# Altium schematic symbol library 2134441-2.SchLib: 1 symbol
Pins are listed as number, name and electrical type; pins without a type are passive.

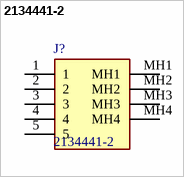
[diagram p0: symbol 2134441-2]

## 2134441-2
designator J?
Body Features: Offset .88 MM | Shell Plating Material Tin over Nickel | Shell Plating Finish Matte | Connector Profile Micro | Configuration Features: Number of Positions 5 | Number of Ports 1 | Contact Features: Contact Mating Area Plating Material Thickness .76 MICM | Contact Current Rating (Max) 1.8 AMP | Contact Mating Area Plating Material Gold | Contact Mating Area Plating Material Thickness 29.52 MICIN | Dimensions: PCB Thickness (Recommended) .8  1. MM | PCB Thickness (Recommended) .031  .039; Manufacturer_Name: TE Connectivity; Geometry.Height: 1.9mm
footprint 21344412
pins: 1, 2, 3, 4, 5, MH1, MH2, MH3, MH4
